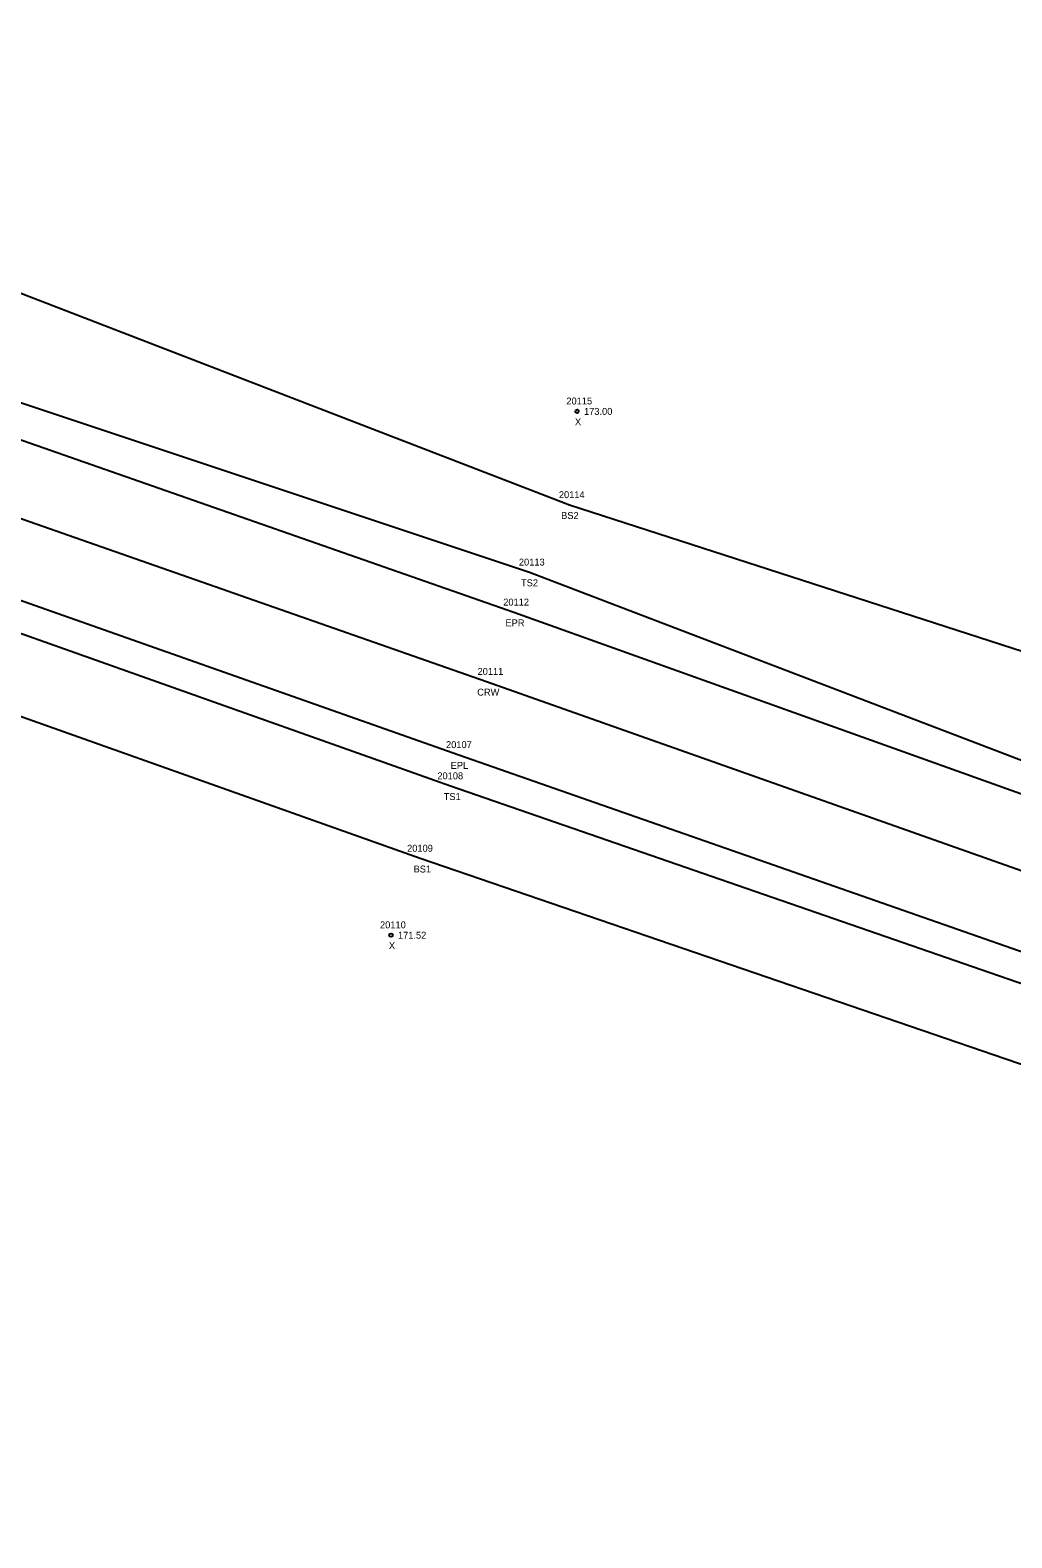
# Model space of a CAD drawing. Extents: x 2054705 to 2055845, y 756616 to 757058.
# Drawn here: x 2054847.2 to 2054988.9, y 756838.4 to 757056.1 of the extents above; entities that cross this region are included whole.
import ezdxf

# ---------------------------------------------------------------- set-up
doc = ezdxf.new("R2010")
doc.units = 0
for name, color, linetype in [('RD_DTM_BkLn1', 7, 'Continuous'), ('RD_DTM_BkLn2', 7, 'Continuous'), ('RD_EX_Road', 7, 'Continuous'), ('RD_EX_Road_txCode', 7, 'Continuous'), ('RD_Sketch8', 7, 'Continuous'), ('RD_SMD_Locator', 7, 'Continuous'), ('RD_SMD_Misc', 7, 'Continuous')]:
    doc.layers.add(name, color=color, linetype=linetype)

msp = doc.modelspace()

# ---------------------------------------------------------------- linework, layer by layer
at = {"layer": 'RD_DTM_BkLn1'}
msp.add_lwpolyline([(2055198.36, 756861.7), (2055105.78, 756894.05), (2055007.93, 756928.48), (2054913.01, 756962.02), (2054814.44, 756996.55), (2054720.09, 757029.92)], dxfattribs=at)
at = {"layer": 'RD_DTM_BkLn2'}
for points in [[(2055211.27, 756885.1), (2055111.97, 756928.98), (2055016.09, 756958.06), (2054925.03, 756987.54), (2054823.8, 757026.56), (2054727.34, 757056.13)], [(2055202.66, 756871.32), (2055205.34, 756878.01), (2055110.35, 756912.5), (2055013.19, 756941.9), (2054919.26, 756977.81), (2054820.17, 757010.81), (2054725.86, 757045.67)], [(2055194.23, 756850.45), (2055191.32, 756843.16), (2055102.38, 756877.36), (2055003.34, 756913.89), (2054907.82, 756946.94), (2054809.11, 756982.01), (2054715.58, 757014.67)], [(2055191.63, 756838.39), (2055097.99, 756868.2), (2055000.1, 756903.36), (2054903.44, 756936.48), (2054804.9, 756971.5), (2054712.86, 757006.97)]]:
    msp.add_lwpolyline(points, dxfattribs=at)
at = {"layer": 'RD_EX_Road'}
for points in [[(2055198.36, 756861.7), (2055202.66, 756871.32), (2055108.14, 756904.32), (2055012.29, 756937.9), (2054917, 756972.03), (2054818.52, 757006.44), (2054723.95, 757039.68)], [(2055198.36, 756861.7), (2055194.23, 756850.45), (2055102.54, 756883.31), (2055004.69, 756917.96), (2054909.06, 756951.44), (2054810.65, 756986.13), (2054717.55, 757018.91)]]:
    msp.add_lwpolyline(points, dxfattribs=at)
at = {"layer": 'RD_SMD_Locator'}
for centre, radius in [((2054926.11, 757001.07), 0.25), ((2054925.03, 756987.54), 0.001), ((2054919.26, 756977.81), 0.001), ((2054917, 756972.03), 0.001), ((2054913.01, 756962.02), 0.001), ((2054909.06, 756951.44), 0.001), ((2054907.82, 756946.94), 0.001), ((2054903.44, 756936.48), 0.001), ((2054899.25, 756925.42), 0.25)]:
    msp.add_circle(centre, radius, dxfattribs=at)

# ---------------------------------------------------------------- texts
at = {"layer": 'RD_EX_Road_txCode'}
for s, p in [('20112', (2054915.45, 756973.03)), ('EPR', (2054915.77, 756970.03)), ('20107', (2054907.19, 756952.44)), ('EPL', (2054907.86, 756949.44))]:
    msp.add_text(s, height=1, dxfattribs=at).set_placement(p)
at = {"layer": 'RD_Sketch8'}
for s, p in [('20115', (2054924.56, 757002.07)), ('173.00', (2054927.11, 757000.57)), ('X', (2054925.8, 756999.07)), ('20110', (2054897.66, 756926.42)), ('X', (2054898.94, 756923.42)), ('171.52', (2054900.25, 756924.92))]:
    msp.add_text(s, height=1, dxfattribs=at).set_placement(p)
at = {"layer": 'RD_SMD_Misc'}
for s, p in [('20114', (2054923.48, 756988.54)), ('BS2', (2054923.8, 756985.54)), ('20113', (2054917.71, 756978.81)), ('TS2', (2054918.02, 756975.81)), ('20111', (2054911.74, 756963.02)), ('CRW', (2054911.69, 756960.02)), ('20108', (2054905.94, 756947.94)), ('TS1', (2054906.86, 756944.94)), ('20109', (2054901.57, 756937.48)), ('BS1', (2054902.5, 756934.48))]:
    msp.add_text(s, height=1, dxfattribs=at).set_placement(p)

doc.saveas('drawing.dxf')
